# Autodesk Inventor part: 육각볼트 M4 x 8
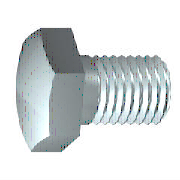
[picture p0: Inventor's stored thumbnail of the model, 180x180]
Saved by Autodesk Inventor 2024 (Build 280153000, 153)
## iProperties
Created: 2012-02
Part Number: 육각볼트 M4 x 8
Material: 강철, 연강
Description: 6각 머리 나사
Document SubType Name: Modeling
Standard: ISO 4017
Designer: mduedu
Standard Revision: Third edition 1999-08-15
Standards Organization: ISO
Language: ko-KR
Size Designation: M4 x 10
Categories: <MemberInstance><Categories><Category DisplayName="조임쇠" InternalName="e4da775c-781d-43d5-af7c-5136215cf5a6" Mnemonic="FSTN"><Category DisplayName="볼트" InternalN
Density: 7.86 g/cm^3
Appearance: 반광택
IsCustomPart: 0
Author: mduedu
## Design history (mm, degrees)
revolve "본체" stored, may be unused: angle "d12" = 90 deg
sketch "스케치2"
  geometry: L1 (0, 4.041)-(3.5, 2.021); L2 (3.5, 2.021)-(3.5, -2.021); L3 (3.5, -2.021)-(0, -4.041); L4 (0, -4.041)-(-3.5, -2.021); L5 (-3.5, -2.021)-(-3.5, 2.021); L6 (-3.5, 2.021)-(0, 4.041); 2 further points
  constraints: 12 end point, 1 coincident, 1 vertical, 11 other
  dimensions: "d11" = 7 distance between parallel lines of L5 L2 (= SW)
extrude "머리" join sketch "스케치2" distance "d3" = 2.4 (= KOH - SD); taper "d4" = 0 deg
revolve "모따기1" stored, may be unused: angle "d21" = 90 deg
workplane "Work Plane1"
body "Solid1"
feature "스레드" dims "d15" = 6.25 (= GEL), "d16" = 0
chamfer "모따기2" distance "d6" = 0.42941 (= -0.5 x SPD + 0.5 x GD); stored, may be unused: second distance "d7" = 0.42952 (computed from GUL), angle "d55" = 45 deg
sketch "스케치1"
  geometry: L1 (0, 3.015)-(0, 2); L2 (1.75, 2)-(8, 2); L3 (8, 2)-(8, 0); L4 (8, 0)-(-0.4, 0); L5 (-2.08, 0)-(9.68, 0) reference; L6 (-0.4, 0)-(-0.4, 3.015); L7 (-0.4, 3.015)-(0, 3.015); L8 (1.75, 2)-(1.32, 2); L9 (1.32, 2)-(0, 2); L10 (0, -0.603)-(0, 3.618) reference
  constraints: 16 end point, 2 collinear, 2 perpendicular, 1 parallel
  dimensions: "d0" = 8 distance between parallel lines of L3 L1 (= NLG); "d1" = 6.25 distance from line of L2.start L3 (= GEL); "d2" = 4 diameter of L2 L4 (= GD); "d9" = 0.4001 distance between parallel lines of L6 L1 (computed from SD); "d10" = 6.03 diameter of L7 L4 (= SD2); "d13" = 0.42952 distance of L2.start L8.end (computed from GAL); "d14" = 4 diameter of L9 L4 (= BDM)
sketch "스케치4"
  geometry: L1 (-2.8, 3.5)-(-2.8, 4.041); L2 (-2.8, 4.041)-(-2.487, 4.041); L3 (-2.487, 4.041)-(-2.8, 3.5); L4 (-3.28, 0)-(0.08, 0) reference; L5 (-0.4, 4.041)-(-2.8, 4.041) reference; L6 (-2.8, 2.021)-(-2.8, 4.041) reference
  constraints: 6 end point, 2 collinear, 1 perpendicular, 1 vertical
  dimensions: "d5" = 30 deg angle of L3 L1 (= ANG1); "d19" = 7 diameter of L1.start L4 (= SW0)
other parameters: "NLG" = 8 [user parameter; used in 1 equation term], "GD" = 4 (= NND) [user parameter; used in 2 equation terms], "BDM" = 4 (= NND) [user parameter; used in 1 equation term], "KOH" = 2.8 [user parameter; used in 1 equation term], "GEL" = 6.25 [user parameter; used in 2 equation terms], "SW" = 7 [user parameter; used in 2 equation terms], "SW0" = 7 (= SW) [user parameter; used in 1 equation term], "SPD" = 3.14117 (= NND - 1.2269 x PTC) [user parameter; used in 1 equation term], "SD2" = 6.03 [user parameter; used in 2 equation terms], "SD" = 0.4 [user parameter; used in 2 equation terms], "ANG1" = 30 deg [user parameter; used in 1 equation term], "GAL" = 0.42941 (= 0.61345 x PTC) [user parameter; used in 1 equation term], "GUL" = 0.42941 (= 0.61345 x PTC) [user parameter; used in 1 equation term], "d8" = 0, "RR" = 0.2 [user parameter], "d57" = 0, "d58" = 0, "TPU" = 14.28571 (computed from PTC) [user parameter], "GD1" = 3.14117 (= THREADDIA - 1.2269 x PTC) [user parameter], "THREADDIA" = 4 [user parameter; used in 1 equation term], "SDH" = 6.03 (= SD2) [user parameter], "SDHG" = 2.1 [user parameter], "TOA" = 30 deg [user parameter], "PTC" = 0.7 [user parameter; used in 5 equation terms], "NND" = 4 [user parameter; used in 3 equation terms], "E0" = 8.085 [user parameter]
